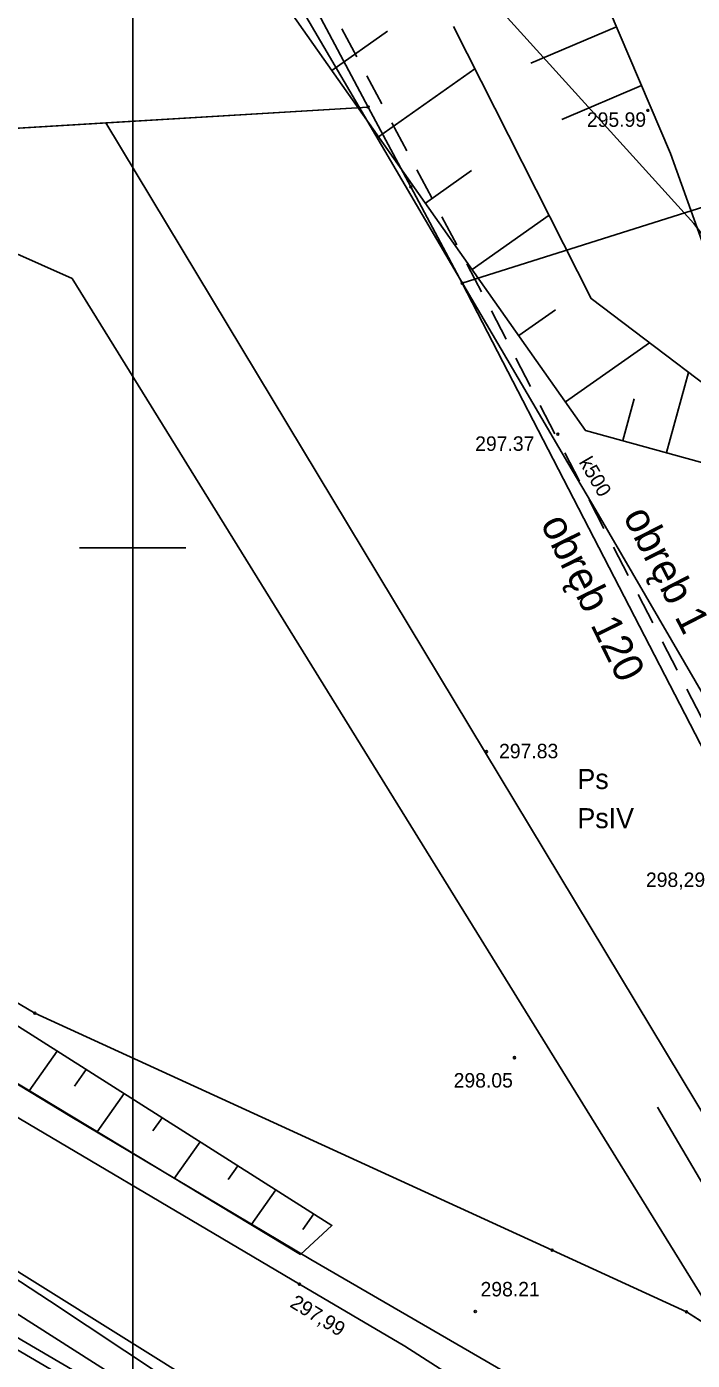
# Model space of a CAD drawing. Extents: x 7477803 to 7478145, y 5500698 to 5500984.
# Drawn here: x 7477995 to 7478026.3, y 5500861.8 to 5500924.5 of the extents above; entities that cross this region are included whole.
import ezdxf

# ---------------------------------------------------------------- set-up
doc = ezdxf.new("R2010")
doc.units = 0
for name, color, linetype in [('203-Punkt załamania granicy działki nie stabilizowany', 7, 'Continuous'), ('eNN', 7, 'Continuous'), ('gr_dzialki', 7, 'Continuous'), ('gr_klasy', 7, 'Continuous'), ('jezdnia', 7, 'Continuous'), ('k', 7, 'Continuous'), ('k_opis', 7, 'Continuous'), ('nr_obrebu', 7, 'Continuous'), ('opis_klasy', 7, 'Continuous'), ('opis_uzytek', 7, 'Continuous'), ('pkt_wys', 7, 'Continuous'), ('pob_gr_obrebu', 7, 'Continuous'), ('robocza49', 7, 'Continuous'), ('rowy', 7, 'Continuous'), ('skarp_wypel', 7, 'Continuous'), ('skarpa_gora', 7, 'Continuous'), ('w', 7, 'Continuous'), ('warst_ciagla', 7, 'Continuous'), ('zakresy', 7, 'Continuous')]:
    doc.layers.add(name, color=color, linetype=linetype)

# ---------------------------------------------------------------- blocks, each defined once
blk = doc.blocks.new('203')
blk.add_circle((0, 0), 0.045)
blk = doc.blocks.new('801_3')
at = {"layer": 'pkt_wys'}
blk.add_circle((0, 0), 0.045, dxfattribs=at)
blk.add_circle((0, 0), 0.045, dxfattribs=at)
blk = doc.blocks.new('801_5')
at = {"layer": 'pkt_wys'}
blk.add_circle((0, 0), 0.05, dxfattribs=at)
blk.add_circle((0, 0), 0.05, dxfattribs=at)
blk = doc.blocks.new('801_5_2')
at = {"layer": 'pkt_wys'}
blk.add_circle((0, 0), 0.05, dxfattribs=at)
blk.add_circle((0, 0), 0.05, dxfattribs=at)

msp = doc.modelspace()

# ---------------------------------------------------------------- linework, layer by layer
at = {"layer": 'eNN'}
msp.add_lwpolyline([(7478044.292, 5500829.332), (7478043.979, 5500830.08), (7478036.967, 5500842.126), (7478033.374, 5500847.92), (7478030.266, 5500851.792), (7478027.179, 5500855.154), (7478025.031, 5500856.9), (7478008.369, 5500866.572), (7477997.07, 5500873.297), (7477990.438, 5500877.31), (7477980.374, 5500883.358), (7477966.627, 5500891.122), (7477956.111, 5500897.36), (7477948.099, 5500902.324), (7477944.454, 5500904.573)], dxfattribs=at)
at = {"layer": 'gr_dzialki'}
for points in [[(7477996.18, 5500948.69), (7478011.06, 5500920.71)], [(7477963.71, 5500917.85), (7478011.06, 5500920.71)], [(7478011.06, 5500920.71), (7478013.06, 5500916.96)], [(7478015.47, 5500912.43), (7478032.565, 5500917.83)], [(7478015.47, 5500912.43), (7478013.06, 5500916.96)], [(7478040.21, 5500864.57), (7478015.47, 5500912.43)], [(7477995.4, 5500878.14), (7477967.16, 5500894.83)], [(7478019.7, 5500867), (7477995.4, 5500878.14)], [(7478026.01, 5500864.11), (7478019.7, 5500867)], [(7478040.72, 5500854.66), (7478026.01, 5500864.11)]]:
    msp.add_lwpolyline(points, dxfattribs=at)
at = {"layer": 'gr_klasy'}
for points in [[(7478011.06, 5500920.71), (7477996.18, 5500948.69)], [(7478011.06, 5500920.71), (7477998.73, 5500919.96)], [(7478013.06, 5500916.96), (7478011.06, 5500920.71)], [(7477963.71, 5500917.85), (7477998.73, 5500919.96)], [(7477998.73, 5500919.96), (7478036.42, 5500857.42)], [(7478015.47, 5500912.43), (7478013.06, 5500916.96)], [(7477997.16, 5500912.65), (7477994.27, 5500913.94)], [(7478027.95, 5500862.87), (7477997.16, 5500912.65)], [(7478040.21, 5500864.57), (7478015.47, 5500912.43)], [(7477967.16, 5500894.83), (7477995.4, 5500878.14)], [(7477995.4, 5500878.14), (7478019.7, 5500867)], [(7478019.7, 5500867), (7478026.01, 5500864.11)], [(7478026.01, 5500864.11), (7478027.95, 5500862.87)]]:
    msp.add_lwpolyline(points, dxfattribs=at)
at = {"layer": 'jezdnia'}
for points in [[(7477991.46, 5500875.087), (7478007.83, 5500865.404), (7478012.783, 5500862.5)], [(7478010.61, 5500855.711), (7478003.516, 5500860.43), (7477987.535, 5500870.412)], [(7478012.783, 5500862.5), (7478017.927, 5500859.186), (7478021.58, 5500856.7), (7478025.873, 5500853.334), (7478028.356, 5500850.967), (7478030.699, 5500848.349), (7478032.422, 5500845.441), (7478033.114, 5500843.932), (7478033.826, 5500841.963), (7478034.518, 5500839.904), (7478035.522, 5500835.985), (7478035.876, 5500832.755), (7478035.757, 5500831.475), (7478035.341, 5500827.995), (7478034.495, 5500824.894), (7478032.649, 5500820.712), (7478031.642, 5500818.53)]]:
    msp.add_lwpolyline(points, dxfattribs=at)
at = {"layer": 'k'}
msp.add_line((7477991.676, 5500953.076), (7478020.436, 5500903.997), dxfattribs=at)
for points in [[(7478020.436, 5500903.997), (7478021.747, 5500901.762), (7478045.913, 5500860.252)], [(7477999.978, 5500860.567), (7477987.079, 5500868.79)]]:
    msp.add_lwpolyline(points, dxfattribs=at)
at = {"layer": 'pob_gr_obrebu'}
for p, q in [((7478009.823, 5500924.385), (7478010.527, 5500923.06)), ((7478010.997, 5500922.177), (7478011.701, 5500920.853)), ((7478012.171, 5500919.97), (7478012.875, 5500918.645)), ((7478013.344, 5500917.762), (7478014.049, 5500916.438)), ((7478014.518, 5500915.555), (7478015.222, 5500914.231)), ((7478016.848, 5500911.132), (7478017.537, 5500909.799)), ((7478017.996, 5500908.911), (7478018.685, 5500907.578)), ((7478019.145, 5500906.69), (7478019.833, 5500905.357)), ((7478020.293, 5500904.469), (7478020.981, 5500903.137)), ((7478021.441, 5500902.248), (7478022.129, 5500900.916)), ((7478022.589, 5500900.027), (7478023.277, 5500898.695)), ((7478023.737, 5500897.807), (7478024.425, 5500896.474)), ((7478024.885, 5500895.586), (7478025.573, 5500894.253)), ((7478026.033, 5500893.365), (7478026.722, 5500892.032))]:
    msp.add_line(p, q, dxfattribs=at)
msp.add_lwpolyline([(7478015.692, 5500913.348), (7478016.092, 5500912.595), (7478016.389, 5500912.02)], dxfattribs=at)
at = {"layer": 'robocza49'}
for p, q in [((7478000, 5500750), (7478000, 5500973.047)), ((7477997.5, 5500900), (7478000, 5500900)), ((7478000, 5500900), (7478002.5, 5500900))]:
    msp.add_line(p, q, dxfattribs=at)
at = {"layer": 'rowy'}
for points in [[(7477993.629, 5500862.871), (7478006.577, 5500855.288)], [(7477993.882, 5500863.302), (7478006.843, 5500855.712)]]:
    msp.add_lwpolyline(points, dxfattribs=at)
at = {"layer": 'skarp_wypel'}
for p, q in [((7478009.359, 5500922.426), (7478011.971, 5500924.266)), ((7478022.724, 5500924.481), (7478018.698, 5500922.77)), ((7478011.552, 5500919.311), (7478016.075, 5500922.497)), ((7478023.897, 5500921.72), (7478020.154, 5500920.129)), ((7478013.746, 5500916.197), (7478015.914, 5500917.723)), ((7478015.94, 5500913.082), (7478019.555, 5500915.628)), ((7478018.133, 5500909.968), (7478019.856, 5500911.181)), ((7478020.327, 5500906.853), (7478024.274, 5500909.633)), ((7478025.071, 5500904.471), (7478026.111, 5500908.243)), ((7478023.02, 5500905.036), (7478023.561, 5500907)), ((7477996.446, 5500876.359), (7477995.133, 5500874.491)), ((7477997.814, 5500875.491), (7477997.269, 5500874.715)), ((7477999.596, 5500874.36), (7477998.331, 5500872.56)), ((7478001.379, 5500873.229), (7478000.945, 5500872.612)), ((7478003.161, 5500872.098), (7478001.95, 5500870.375)), ((7478004.943, 5500870.967), (7478004.486, 5500870.317)), ((7478006.726, 5500869.836), (7478005.568, 5500868.19)), ((7478008.508, 5500868.705), (7478007.994, 5500867.974))]:
    msp.add_line(p, q, dxfattribs=at)
at = {"layer": 'skarpa_gora'}
msp.add_line((7478025.254, 5500918.53), (7478029.997, 5500905.289), dxfattribs=at)
for points in [[(7478007.879, 5500866.795), (7478009.357, 5500868.166), (7477985.351, 5500883.4), (7477939.898, 5500913.11), (7477944.561, 5500919.785), (7477954.951, 5500928.707), (7477971.014, 5500935.434), (7477981.218, 5500940.405), (7477991.643, 5500944.907), (7477994.866, 5500942.92), (7478002.778, 5500931.769), (7478021.266, 5500905.519), (7478029.289, 5500903.308), (7478032.779, 5500894.332), (7478047.773, 5500881.148)], [(7478007.879, 5500866.795), (7477984.093, 5500881.159), (7477934.83, 5500911.735), (7477933.524, 5500917.153), (7477941.313, 5500926.602), (7477947.253, 5500931.749), (7477948.257, 5500932.619)], [(7478021.395, 5500927.609), (7478025.254, 5500918.53)], [(7478047.773, 5500881.148), (7478035.389, 5500893.665), (7478029.997, 5500905.289), (7478021.54, 5500911.709), (7478015.067, 5500924.486)]]:
    msp.add_lwpolyline(points, dxfattribs=at)
at = {"layer": 'w'}
for points in [[(7478024.653, 5500873.716), (7478028.65, 5500866.944), (7478037.871, 5500851.488), (7478050.775, 5500839.571), (7478051.315, 5500839.075), (7478052.898, 5500837.629)], [(7478023.125, 5500842.409), (7478018.943, 5500849.443), (7477996.094, 5500864.625), (7477987.395, 5500870.305)]]:
    msp.add_lwpolyline(points, dxfattribs=at)
at = {"layer": 'warst_ciagla'}
msp.add_lwpolyline([(7478024.222, 5500920.548), (7478024.222, 5500920.551)], dxfattribs=at)
at = {"layer": 'zakresy'}
msp.add_lwpolyline([(7477995.059, 5500962.348), (7477983.951, 5500968.084), (7477970.781, 5500968.613), (7477936.09, 5500958.171), (7477930.511, 5500954.336), (7477914.305, 5500958.58), (7477904.32, 5500957.41), (7477897.265, 5500950.868), (7477811.424, 5500829.338), (7477936.003, 5500769.492), (7478008.982, 5500726.585), (7478019.402, 5500721.781), (7478037.95, 5500734.97), (7478039.493, 5500755.094), (7478043.98, 5500765.708), (7478067.545, 5500795.068), (7478092.109, 5500820.25), (7478076.156, 5500837.989), (7478068.105, 5500851.146), (7478061.422, 5500873.298), (7478054.135, 5500876.371), (7478039.669, 5500897.644), (7478026.36, 5500915.23), (7478015.054, 5500927.728)], close=True, dxfattribs=at)

# ---------------------------------------------------------------- block references
at = {"layer": '203-Punkt załamania granicy działki nie stabilizowany'}
for p in [(7478011.06, 5500920.71), (7478013.06, 5500916.96), (7478015.47, 5500912.43), (7477995.4, 5500878.14), (7478019.7, 5500867), (7478026.01, 5500864.11)]:
    msp.add_blockref('203', p, dxfattribs=at)
at = {"layer": 'pkt_wys', "rotation": 0.0626175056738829}
for name, p in [('801_3', (7478024.2, 5500920.552)), ('801_5', (7478019.967, 5500905.338)), ('801_5', (7478016.613, 5500890.424)), ('801_5', (7478017.929, 5500876.046)), ('801_5_2', (7478007.83, 5500865.404)), ('801_5', (7478016.092, 5500864.124))]:
    msp.add_blockref(name, p, dxfattribs=at)

# ---------------------------------------------------------------- texts
at = {"layer": 'k_opis'}
msp.add_text('k500', height=0.68, rotation=300.39023, dxfattribs=at).set_placement((7478020.937, 5500904.027))
at = {"layer": 'nr_obrebu'}
for s, rotation, p in [('obręb 1', 297.16567, (7478023.01, 5500901.486)), ('obręb 120', 296.24496, (7478019.135, 5500901.146))]:
    msp.add_text(s, height=1.4, rotation=rotation, dxfattribs=at).set_placement(p)
at = {"layer": 'opis_klasy'}
msp.add_text('PsIV', height=0.94, dxfattribs=at).set_placement((7478020.89, 5500886.83))
at = {"layer": 'opis_uzytek'}
msp.add_text('Ps', height=0.94, dxfattribs=at).set_placement((7478020.89, 5500888.67))
at = {"layer": 'pkt_wys'}
for s, rotation, p in [('295.99', 0.06262, (7478021.334, 5500919.777)), ('297.37', 0.06262, (7478016.086, 5500904.555)), ('297.83', 0.06262, (7478017.208, 5500890.111)), ('298,29', 0.06262, (7478024.107, 5500884.066)), ('298.05', 0.06262, (7478015.075, 5500874.643)), ('298.21', 0.06262, (7478016.339, 5500864.832)), ('297,99', 328.63883, (7478007.335, 5500864.371))]:
    msp.add_text(s, height=0.68, rotation=rotation, dxfattribs=at).set_placement(p)

doc.saveas('drawing.dxf')
